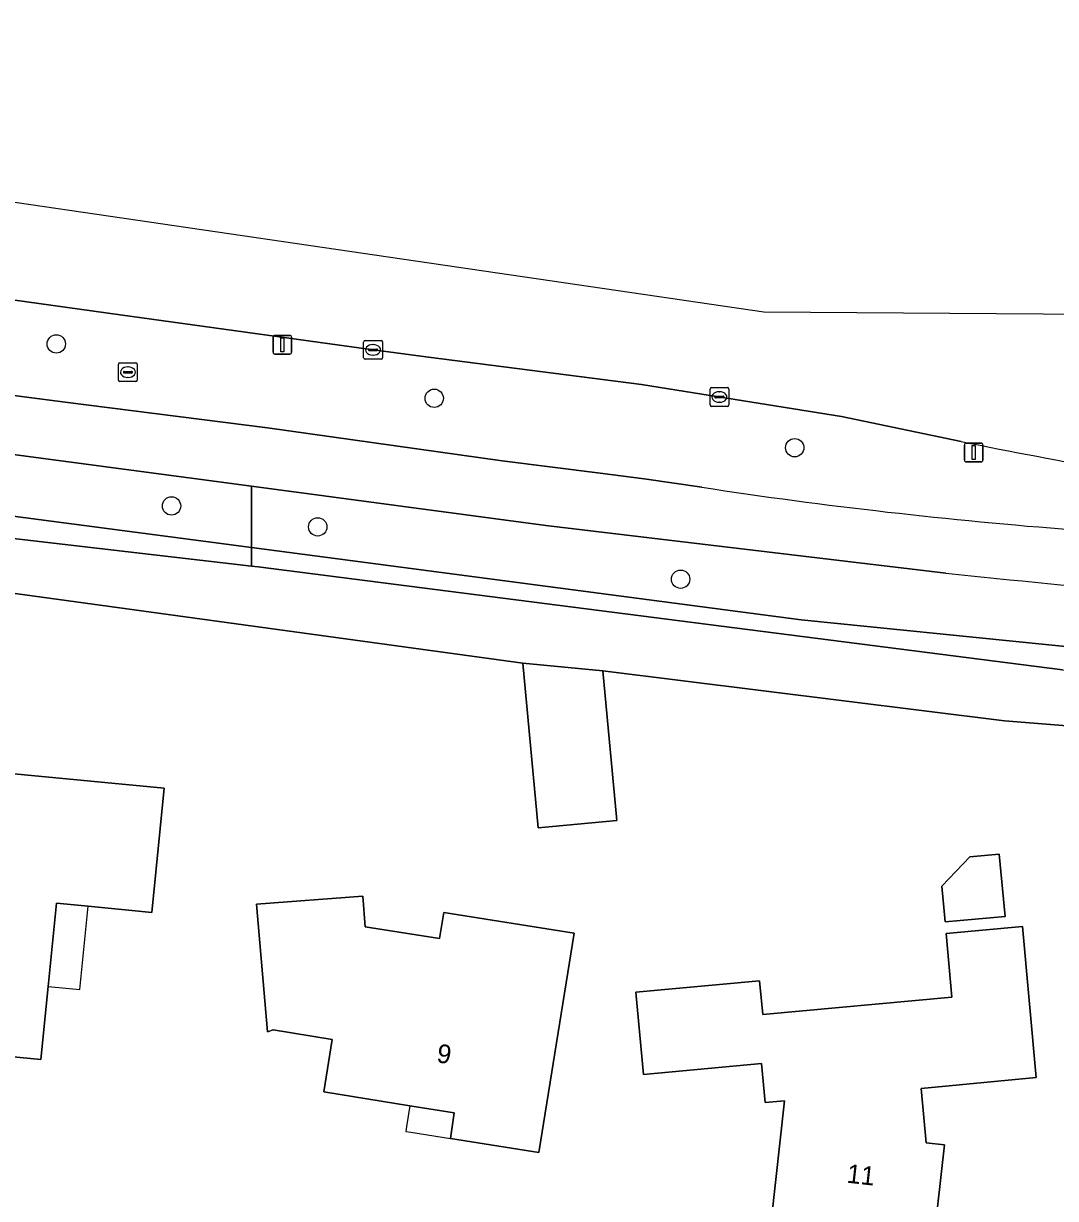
# Model space of a CAD drawing. Extents: x 162156 to 163172, y 378995 to 380779.
# Drawn here: x 162325.6 to 162380.6, y 380696.9 to 380759.6 of the extents above; entities that cross this region are included whole.
import ezdxf

# ---------------------------------------------------------------- set-up
doc = ezdxf.new("R2010")
doc.units = 0
for name, color, linetype in [('IMGEO_Berm_groen', 7, 'Continuous'), ('IMGEO_Boom', 7, 'Continuous'), ('IMGEO_Erf', 7, 'Continuous'), ('IMGEO_Fietspad_open', 7, 'Continuous'), ('IMGEO_Groenvoorziening', 7, 'Continuous'), ('IMGEO_Kolk', 7, 'Continuous'), ('IMGEO_Lichtmast', 7, 'Continuous'), ('IMGEO_Pand', 7, 'Continuous'), ('IMGEO_Pand_nummerreeks', 7, 'Continuous'), ('IMGEO_Pand_overbouw', 7, 'Continuous'), ('IMGEO_Rijbaan_lokaal_gesloten', 7, 'Continuous'), ('IMGEO_Rioolput', 7, 'Continuous')]:
    doc.layers.add(name, color=color, linetype=linetype)

msp = doc.modelspace()

# ---------------------------------------------------------------- linework, layer by layer
at = {"layer": 'IMGEO_Berm_groen'}
for points in [[(162369.167, 380738.615), (162362.168, 380739.733), (162358.509, 380740.318), (162347.146, 380741.785), (162344.082, 380742.181), (162330.715, 380744.032), (162309.765, 380746.955), (162296.482, 380748.633), (162293.983, 380746.475)], [(162266.518, 380747.721), (162277.284, 380746.222), (162298.393, 380743.379), (162314.638, 380741.08), (162327.765, 380739.371), (162338.555, 380738.008), (162351.072, 380736.25), (162356.297, 380735.58), (162356.856, 380735.509), (162358.655, 380735.278), (162361.722, 380734.839)], [(162375.561, 380737.276), (162369.167, 380738.615)], [(162374.742, 380730.259), (162353.401, 380732.804), (162337.707, 380734.894), (162337.707, 380731.624), (162367.032, 380727.767), (162393.091, 380725.139), (162396.479, 380724.928), (162396.479, 380728.385)]]:
    msp.add_lwpolyline(points, dxfattribs=at)
msp.add_lwpolyline([(162308.145, 380738.83), (162266.965, 380744.633), (162266.661, 380742.106), (162269.554, 380741.596), (162281.129, 380739.553), (162292.495, 380737.993), (162303.418, 380735.729), (162310.512, 380735.2), (162337.707, 380731.624), (162337.707, 380734.894)], close=True, dxfattribs=at)
for centre, radius, start, end in [((162457.506, 381145.809), 416.67, 258.65791, 260.92168), ((162401.841, 380997.543), 265.75, 261.31722, 265.62412), ((162429.113, 381233.916), 506.583, 263.83866, 266.30648)]:
    msp.add_arc(centre, radius, start, end, dxfattribs=at)
at = {"layer": 'IMGEO_Boom'}
for centre in [(162327.301, 380742.484), (162347.454, 380739.582), (162366.681, 380736.948), (162333.446, 380733.842), (162341.244, 380732.725), (162360.594, 380729.933)]:
    msp.add_circle(centre, 0.489, dxfattribs=at)
at = {"layer": 'IMGEO_Erf'}
msp.add_lwpolyline([(162456.195, 380687.817), (162455.268, 380702.293), (162454.7, 380711.173), (162451.171, 380717.827), (162447.539, 380719.38), (162421.077, 380719.983), (162399.253, 380720.671), (162377.872, 380722.381), (162356.445, 380725.051), (162357.192, 380717.064), (162353.005, 380716.672), (162352.183, 380725.459), (162315.245, 380730.525), (162304.371, 380721.939), (162302.171, 380699.713), (162301.962, 380699.607), (162295.473, 380636.096)], dxfattribs=at)
for points in [[(162332.391, 380712.153), (162329.003, 380712.487), (162327.315, 380712.654), (162326.871, 380708.208), (162326.482, 380704.316), (162321.505, 380704.795), (162318.143, 380705.118), (162318.555, 380709.399), (162318.912, 380713.112), (162317.419, 380713.256), (162317.945, 380718.721), (162321.529, 380718.377), (162321.673, 380719.871), (162333.045, 380718.777)], [(162374.706, 380711.648), (162374.53, 380713.554), (162376.016, 380715.118), (162377.589, 380715.264), (162377.896, 380711.943)], [(162353.038, 380699.342), (162348.33, 380700.09), (162348.525, 380701.463), (162346.156, 380701.846), (162341.573, 380702.588), (162342.02, 380705.382), (162338.87, 380705.886), (162338.566, 380705.795), (162337.971, 380712.599), (162343.655, 380713.025), (162343.769, 380711.397), (162347.739, 380710.763), (162347.963, 380712.154), (162354.91, 380711.043)], [(162374.1, 380694.692), (162365.427, 380695.652), (162366.143, 380702.113), (162365.098, 380702.015), (162364.905, 380704.096), (162358.613, 380703.506), (162358.201, 380707.901), (162364.81, 380708.514), (162364.977, 380706.712), (162375.064, 380707.644), (162374.75, 380711.028), (162378.83, 380711.405), (162379.554, 380703.358), (162373.417, 380702.773), (162373.696, 380699.859), (162374.66, 380699.752)]]:
    msp.add_lwpolyline(points, close=True, dxfattribs=at)
at = {"layer": 'IMGEO_Fietspad_open'}
for points in [[(162361.722, 380734.839), (162358.655, 380735.278), (162356.856, 380735.509), (162356.297, 380735.58), (162351.072, 380736.25), (162338.555, 380738.008), (162327.765, 380739.371), (162314.638, 380741.08), (162298.393, 380743.379), (162277.284, 380746.222), (162266.518, 380747.721), (162262.338, 380748.306)], [(162253.923, 380746.456), (162256.265, 380746.136), (162261.032, 380745.421), (162266.965, 380744.633), (162308.145, 380738.83), (162337.707, 380734.894), (162353.401, 380732.804), (162374.742, 380730.259)]]:
    msp.add_lwpolyline(points, dxfattribs=at)
for centre, radius, start, end in [((162401.841, 380997.543), 265.75, 261.31722, 265.62412), ((162429.113, 381233.916), 506.583, 263.83866, 266.30648)]:
    msp.add_arc(centre, radius, start, end, dxfattribs=at)
at = {"layer": 'IMGEO_Groenvoorziening'}
for points in [[(162337.707, 380731.624), (162310.512, 380735.2), (162303.418, 380735.729), (162292.495, 380737.993), (162281.129, 380739.553), (162269.554, 380741.596), (162274.252, 380739.465), (162292.506, 380736.854), (162310.16, 380733.836), (162337.707, 380730.635)], [(162396.479, 380724.928), (162393.091, 380725.139), (162367.032, 380727.767), (162337.707, 380731.624), (162337.707, 380730.635), (162338.065, 380730.593), (162380.959, 380725.101), (162393.395, 380723.986), (162396.479, 380723.869)]]:
    msp.add_lwpolyline(points, close=True, dxfattribs=at)
for points in [[(162380.959, 380725.101), (162338.065, 380730.593), (162337.707, 380730.635), (162310.16, 380733.836)], [(162315.245, 380730.525), (162352.183, 380725.459), (162356.445, 380725.051), (162377.872, 380722.381), (162399.253, 380720.671)]]:
    msp.add_lwpolyline(points, dxfattribs=at)
at = {"layer": 'IMGEO_Kolk'}
for p, q in [((162343.767, 380742.666), (162344.619, 380742.666)), ((162343.692, 380741.74), (162343.692, 380742.592)), ((162343.951, 380742.16), (162343.951, 380742.172)), ((162344.389, 380742.123), (162343.991, 380742.123)), ((162343.994, 380742.209), (162344.392, 380742.209)), ((162344.18, 380742.446), (162344.205, 380742.446)), ((162344.435, 380742.172), (162344.435, 380742.16)), ((162344.693, 380742.592), (162344.693, 380741.74)), ((162344.619, 380741.666), (162343.767, 380741.666)), ((162344.203, 380741.886), (162344.178, 380741.886)), ((162362.238, 380740.152), (162363.09, 380740.152)), ((162362.163, 380739.226), (162362.163, 380740.078)), ((162362.422, 380739.646), (162362.422, 380739.658)), ((162362.86, 380739.609), (162362.462, 380739.609)), ((162362.465, 380739.695), (162362.863, 380739.695)), ((162362.651, 380739.932), (162362.676, 380739.932)), ((162362.906, 380739.658), (162362.906, 380739.646)), ((162363.164, 380740.078), (162363.164, 380739.226)), ((162363.09, 380739.152), (162362.238, 380739.152)), ((162362.674, 380739.372), (162362.649, 380739.372))]:
    msp.add_line(p, q, dxfattribs=at)
for points in [[(162343.767, 380742.666), (162344.619, 380742.666)], [(162343.692, 380741.74), (162343.692, 380742.592)], [(162344.693, 380742.592), (162344.693, 380741.74)], [(162344.619, 380741.666), (162343.767, 380741.666)], [(162362.238, 380740.152), (162363.09, 380740.152)], [(162362.163, 380739.226), (162362.163, 380740.078)], [(162363.164, 380740.078), (162363.164, 380739.226)], [(162363.09, 380739.152), (162362.238, 380739.152)]]:
    msp.add_lwpolyline(points, dxfattribs=at)
for centre, radius, start, end in [((162343.769, 380742.59), 0.0765, 91.55205, 178.44795), ((162343.769, 380742.59), 0.0765, 91.55205, 178.44795), ((162344.617, 380742.59), 0.0765, 1.55205, 88.44795), ((162344.617, 380742.59), 0.0765, 1.55205, 88.44795), ((162343.991, 380742.169), 0.0403, 85.87752, 175.75265), ((162343.988, 380742.159), 0.0366, 178.93798, 274.71019), ((162344.392, 380742.166), 0.043, 264.86636, 352.45326), ((162344.396, 380742.171), 0.0386, 1.73085, 96.63898), ((162343.769, 380741.742), 0.0765, 181.55205, 268.44795), ((162343.769, 380741.742), 0.0765, 181.55205, 268.44795), ((162344.617, 380741.742), 0.0765, 271.55205, 358.44795), ((162344.617, 380741.742), 0.0765, 271.55205, 358.44795), ((162362.24, 380740.076), 0.0765, 91.55205, 178.44795), ((162362.24, 380740.076), 0.0765, 91.55205, 178.44795), ((162363.088, 380740.076), 0.0765, 1.55205, 88.44795), ((162363.088, 380740.076), 0.0765, 1.55205, 88.44795), ((162362.462, 380739.655), 0.0403, 85.87752, 175.75265), ((162362.459, 380739.645), 0.0366, 178.93798, 274.71019), ((162362.863, 380739.652), 0.043, 264.86636, 352.45326), ((162362.867, 380739.657), 0.0386, 1.73085, 96.63898), ((162362.24, 380739.228), 0.0765, 181.55205, 268.44795), ((162362.24, 380739.228), 0.0765, 181.55205, 268.44795), ((162363.088, 380739.228), 0.0765, 271.55205, 358.44795), ((162363.088, 380739.228), 0.0765, 271.55205, 358.44795)]:
    msp.add_arc(centre, radius, start, end, dxfattribs=at)
for centre, major_axis, ratio, start_param, end_param in [((162344.179, 380742.166), (-0.387, 0.002), 0.722429, 4.712389, 7.853982), ((162344.204, 380742.166), (-0.39, 0.002), 0.717154, 1.570796, 4.712389), ((162362.65, 380739.652), (-0.387, 0.002), 0.722429, 4.712389, 7.853982), ((162362.675, 380739.652), (-0.39, 0.002), 0.717154, 1.570796, 4.712389)]:
    msp.add_ellipse(centre, major_axis=major_axis, ratio=ratio, start_param=start_param, end_param=end_param, dxfattribs=at)
at = {"layer": 'IMGEO_Lichtmast'}
for p, q in [((162338.862, 380742.039), (162338.862, 380742.839)), ((162338.862, 380742.839), (162338.862, 380742.039)), ((162338.962, 380742.939), (162339.752, 380742.939)), ((162339.752, 380742.939), (162338.962, 380742.939)), ((162339.852, 380742.839), (162339.852, 380742.039)), ((162339.852, 380742.039), (162339.852, 380742.839)), ((162339.752, 380741.939), (162338.962, 380741.939)), ((162338.962, 380741.939), (162339.752, 380741.939)), ((162375.728, 380736.291), (162375.728, 380737.091)), ((162375.728, 380737.091), (162375.728, 380736.291)), ((162375.828, 380737.191), (162376.618, 380737.191)), ((162376.618, 380737.191), (162375.828, 380737.191)), ((162376.718, 380737.091), (162376.718, 380736.291)), ((162376.718, 380736.291), (162376.718, 380737.091)), ((162376.618, 380736.191), (162375.828, 380736.191)), ((162375.828, 380736.191), (162376.618, 380736.191))]:
    msp.add_line(p, q, dxfattribs=at)
for points in [[(162339.282, 380742.814), (162339.432, 380742.814), (162339.432, 380742.064), (162339.282, 380742.064), (162339.282, 380742.814)], [(162376.148, 380737.066), (162376.298, 380737.066), (162376.298, 380736.316), (162376.148, 380736.316), (162376.148, 380737.066)]]:
    msp.add_lwpolyline(points, dxfattribs=at)
for centre, start, end in [((162338.962, 380742.839), 90, 180), ((162338.962, 380742.839), 90, 180), ((162339.752, 380742.839), 0, 90), ((162339.752, 380742.839), 360, 90), ((162338.962, 380742.039), 180, 270), ((162338.962, 380742.039), 180, 270), ((162339.752, 380742.039), 270, 0), ((162339.752, 380742.039), 270, 0), ((162375.828, 380737.091), 90, 180), ((162375.828, 380737.091), 90, 180), ((162376.618, 380737.091), 0, 90), ((162376.618, 380737.091), 360, 90), ((162375.828, 380736.291), 180, 270), ((162375.828, 380736.291), 180, 270), ((162376.618, 380736.291), 270, 0), ((162376.618, 380736.291), 270, 0)]:
    msp.add_arc(centre, 0.1, start, end, dxfattribs=at)
at = {"layer": 'IMGEO_Pand'}
for points in [[(162356.445, 380725.051), (162352.183, 380725.459), (162353.005, 380716.672), (162357.192, 380717.064)], [(162333.045, 380718.777), (162321.673, 380719.871), (162321.529, 380718.377), (162317.945, 380718.721), (162317.419, 380713.256), (162318.912, 380713.112), (162318.555, 380709.399), (162318.143, 380705.118), (162321.505, 380704.795), (162326.482, 380704.316), (162326.871, 380708.208), (162327.315, 380712.654), (162329.003, 380712.487), (162332.391, 380712.153)], [(162374.53, 380713.554), (162374.706, 380711.648), (162377.896, 380711.943), (162377.589, 380715.264), (162376.016, 380715.118)], [(162348.33, 380700.09), (162353.038, 380699.342), (162354.91, 380711.043), (162347.963, 380712.154), (162347.739, 380710.763), (162343.769, 380711.397), (162343.655, 380713.025), (162337.971, 380712.599), (162338.566, 380705.795), (162338.87, 380705.886), (162342.02, 380705.382), (162341.573, 380702.588), (162346.156, 380701.846), (162348.525, 380701.463)], [(162364.977, 380706.712), (162364.81, 380708.514), (162358.201, 380707.901), (162358.613, 380703.506), (162364.905, 380704.096), (162365.098, 380702.015), (162366.143, 380702.113), (162365.427, 380695.652), (162374.1, 380694.692), (162374.66, 380699.752), (162373.696, 380699.859), (162373.417, 380702.773), (162379.554, 380703.358), (162378.83, 380711.405), (162374.75, 380711.028), (162375.064, 380707.644)]]:
    msp.add_lwpolyline(points, close=True, dxfattribs=at)
at = {"layer": 'IMGEO_Pand_overbouw'}
for points in [[(162329.003, 380712.487), (162327.315, 380712.654), (162326.871, 380708.208), (162328.559, 380708.039)], [(162346.156, 380701.846), (162345.979, 380700.737), (162345.937, 380700.47), (162346.204, 380700.428), (162348.33, 380700.09), (162348.525, 380701.463)]]:
    msp.add_lwpolyline(points, close=True, dxfattribs=at)
at = {"layer": 'IMGEO_Rijbaan_lokaal_gesloten'}
for points in [[(162392.576, 380743.795), (162389.847, 380744), (162365.037, 380744.169), (162300.915, 380753.574), (162249.838, 380759.576), (162249.309, 380754.329)], [(162262.89, 380753.26), (162263.002, 380753.245), (162267.278, 380752.687), (162268.339, 380752.513), (162296.273, 380748.659), (162296.482, 380748.633), (162309.765, 380746.955), (162330.715, 380744.032), (162344.082, 380742.181), (162347.146, 380741.785), (162358.509, 380740.318), (162362.168, 380739.733), (162369.167, 380738.615), (162375.561, 380737.276)]]:
    msp.add_lwpolyline(points, dxfattribs=at)
msp.add_arc((162457.506, 381145.809), 416.67, 258.65791, 260.92168, dxfattribs=at)
at = {"layer": 'IMGEO_Rioolput'}
for p, q in [((162330.62, 380740.548), (162330.62, 380741.4)), ((162330.695, 380741.474), (162331.547, 380741.474)), ((162331.621, 380741.4), (162331.621, 380740.548)), ((162330.879, 380740.968), (162330.879, 380740.98)), ((162331.317, 380740.931), (162330.919, 380740.931)), ((162330.922, 380741.017), (162331.32, 380741.017)), ((162331.108, 380741.254), (162331.133, 380741.254)), ((162331.363, 380740.98), (162331.363, 380740.968)), ((162331.547, 380740.474), (162330.695, 380740.474)), ((162331.131, 380740.694), (162331.106, 380740.694))]:
    msp.add_line(p, q, dxfattribs=at)
for points in [[(162330.62, 380740.548), (162330.62, 380741.4)], [(162330.695, 380741.474), (162331.547, 380741.474)], [(162331.621, 380741.4), (162331.621, 380740.548)], [(162331.547, 380740.474), (162330.695, 380740.474)]]:
    msp.add_lwpolyline(points, dxfattribs=at)
for centre, radius, start, end in [((162330.697, 380741.398), 0.0765, 91.55205, 178.44795), ((162330.697, 380741.398), 0.0765, 91.55205, 178.44795), ((162331.545, 380741.398), 0.0765, 1.55205, 88.44795), ((162331.545, 380741.398), 0.0765, 1.55205, 88.44795), ((162330.919, 380740.977), 0.0403, 85.87752, 175.75265), ((162330.916, 380740.967), 0.0366, 178.93798, 274.71019), ((162331.32, 380740.974), 0.043, 264.86636, 352.45326), ((162331.324, 380740.979), 0.0386, 1.73085, 96.63898), ((162330.697, 380740.55), 0.0765, 181.55205, 268.44795), ((162330.697, 380740.55), 0.0765, 181.55205, 268.44795), ((162331.545, 380740.55), 0.0765, 271.55205, 358.44795), ((162331.545, 380740.55), 0.0765, 271.55205, 358.44795)]:
    msp.add_arc(centre, radius, start, end, dxfattribs=at)
for centre, major_axis, ratio, start_param, end_param in [((162331.107, 380740.974), (-0.387, 0.002), 0.722429, 4.712389, 7.853982), ((162331.132, 380740.974), (-0.39, 0.002), 0.717154, 1.570796, 4.712389)]:
    msp.add_ellipse(centre, major_axis=major_axis, ratio=ratio, start_param=start_param, end_param=end_param, dxfattribs=at)

# ---------------------------------------------------------------- texts
at = {"layer": 'IMGEO_Pand_nummerreeks'}
for s, rotation, p in [('9', 350.80785, (162347.545, 380704.174)), ('11', 353.68374, (162369.424, 380697.744))]:
    msp.add_text(s, height=1, rotation=rotation, dxfattribs=at).set_placement(p)

doc.saveas('drawing.dxf')
